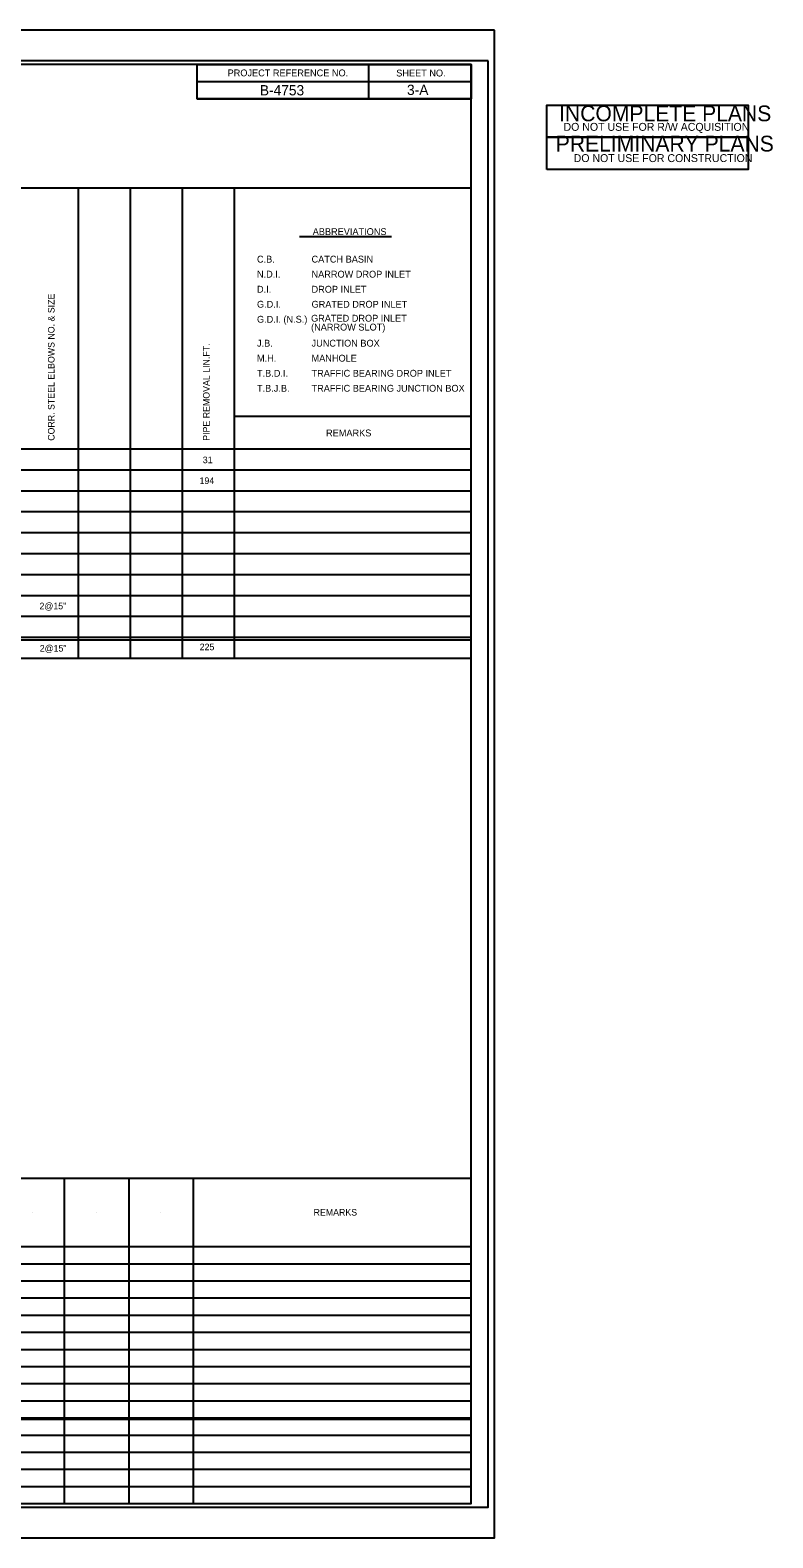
# Model space of a CAD drawing. Extents: x 573867 to 573943.6, y -53322.8 to -53274.5.
# Drawn here: x 573893.88 to 573904.73, y -53322.27 to -53300.27 of the extents above; entities that cross this region are included whole.
import ezdxf

# ---------------------------------------------------------------- set-up
doc = ezdxf.new("R2010")
doc.units = 0
for name, color, linetype in [('Sheet Cutting Line CELL', 7, 'Continuous'), ('Sheet Data Field CELL', 7, 'Continuous'), ('Sheet Pipe Summary CELL', 7, 'Continuous'), ('Sheet Pipe Summary Grid CELL', 7, 'Continuous'), ('Sheet Plot Border Inside CELL', 7, 'Continuous'), ('Sheet Plot Border Outside CELL', 7, 'Continuous'), ('Sheet Sticker Incomplete CELL', 7, 'Continuous'), ('Sheet Sticker Preliminary CELL', 7, 'Continuous'), ('Sheet Summary Combination CELL', 7, 'Continuous'), ('Sheet Summary Combination Grid CELL', 7, 'Continuous'), ('Sheet Summary Guardrail CELL', 7, 'Continuous')]:
    doc.layers.add(name, color=color, linetype=linetype)

msp = doc.modelspace()

# ---------------------------------------------------------------- linework, layer by layer
at = {"layer": 'Sheet Cutting Line CELL'}
for p, q in [((573900.663, -53300.271), (573866.983, -53300.271)), ((573866.983, -53322.271), (573900.663, -53322.271))]:
    msp.add_line(p, q, dxfattribs=at)
at = {"layer": 'Sheet Pipe Summary CELL'}
msp.add_line((573899.158, -53303.289), (573897.818, -53303.289), dxfattribs=at)
at = {"layer": 'Sheet Pipe Summary Grid CELL'}
for p, q in [((573900.323, -53302.578), (573870.323, -53302.58)), ((573894.588, -53309.44), (573894.587, -53302.579)), ((573894.588, -53309.44), (573894.587, -53302.579)), ((573895.348, -53309.44), (573895.347, -53302.579)), ((573895.348, -53309.44), (573895.347, -53302.579)), ((573896.108, -53309.44), (573896.107, -53302.579)), ((573896.108, -53309.44), (573896.107, -53302.579)), ((573896.868, -53309.44), (573896.867, -53302.579)), ((573896.868, -53309.44), (573896.867, -53302.579)), ((573900.323, -53305.91), (573896.868, -53305.91)), ((573900.323, -53306.386), (573870.323, -53306.386)), ((573900.323, -53306.692), (573870.323, -53306.692)), ((573900.323, -53306.997), (573870.323, -53306.997)), ((573900.323, -53307.302), (573870.323, -53307.302)), ((573900.323, -53307.608), (573870.323, -53307.608)), ((573900.323, -53307.913), (573870.323, -53307.913)), ((573900.323, -53308.219), (573870.323, -53308.219)), ((573900.323, -53308.524), (573870.323, -53308.524)), ((573900.323, -53308.829), (573870.323, -53308.829)), ((573900.323, -53309.135), (573870.323, -53309.135)), ((573900.323, -53309.44), (573870.323, -53309.44))]:
    msp.add_line(p, q, dxfattribs=at)
at = {"layer": 'Sheet Plot Border Inside CELL'}
msp.add_lwpolyline([(573900.573, -53300.72), (573867.243, -53300.72), (573867.243, -53321.822), (573900.573, -53321.822)], close=True, dxfattribs=at)
at = {"layer": 'Sheet Plot Border Outside CELL'}
msp.add_lwpolyline([(573900.663, -53300.271), (573866.983, -53300.271), (573866.983, -53322.271), (573900.663, -53322.271)], close=True, dxfattribs=at)
at = {"layer": 'Sheet Sticker Incomplete CELL'}
msp.add_lwpolyline([(573901.428, -53301.835), (573901.428, -53301.365), (573904.368, -53301.365), (573904.368, -53301.835)], close=True, dxfattribs=at)
at = {"layer": 'Sheet Sticker Preliminary CELL'}
msp.add_lwpolyline([(573901.428, -53302.305), (573901.428, -53301.835), (573904.368, -53301.835), (573904.368, -53302.305)], close=True, dxfattribs=at)
at = {"layer": 'Sheet Summary Combination CELL'}
for p, q in [((573898.823, -53300.772), (573898.823, -53301.272)), ((573896.322, -53301.022), (573900.323, -53301.022)), ((573896.322, -53301.272), (573900.323, -53301.272))]:
    msp.add_line(p, q, dxfattribs=at)
for points in [[(573900.323, -53300.771), (573870.323, -53300.771), (573870.323, -53321.771), (573900.323, -53321.771)], [(573896.322, -53300.771), (573900.323, -53300.771), (573900.323, -53301.272), (573896.322, -53301.272)]]:
    msp.add_lwpolyline(points, close=True, dxfattribs=at)
at = {"layer": 'Sheet Summary Combination Grid CELL'}
msp.add_line((573900.323, -53309.171), (573870.323, -53309.171), dxfattribs=at)
at = {"layer": 'Sheet Summary Guardrail CELL'}
for p, q in [((573870.323, -53317.021), (573900.323, -53317.021)), ((573894.381, -53317.021), (573894.381, -53321.771)), ((573895.321, -53317.021), (573895.321, -53321.771)), ((573896.261, -53317.021), (573896.261, -53321.771)), ((573893.911, -53317.521), (573893.911, -53317.521)), ((573894.851, -53317.521), (573894.851, -53317.521)), ((573895.791, -53317.521), (573895.791, -53317.521)), ((573870.323, -53318.021), (573900.323, -53318.021)), ((573870.323, -53318.271), (573900.323, -53318.271)), ((573870.323, -53318.521), (573900.323, -53318.521)), ((573870.323, -53318.771), (573900.323, -53318.771)), ((573870.323, -53319.021), (573900.323, -53319.021)), ((573870.323, -53319.271), (573900.323, -53319.271)), ((573870.323, -53319.521), (573900.323, -53319.521)), ((573876.353, -53319.771), (573900.323, -53319.771)), ((573870.323, -53320.021), (573900.323, -53320.021)), ((573870.323, -53320.271), (573900.323, -53320.271)), ((573870.323, -53320.521), (573900.323, -53320.521)), ((573870.323, -53320.539), (573900.323, -53320.539)), ((573876.353, -53320.771), (573900.323, -53320.771)), ((573870.323, -53321.021), (573900.323, -53321.021)), ((573870.323, -53321.271), (573900.323, -53321.271)), ((573870.323, -53321.521), (573900.323, -53321.521)), ((573870.323, -53321.771), (573900.323, -53321.771))]:
    msp.add_line(p, q, dxfattribs=at)

# ---------------------------------------------------------------- texts
at = {"layer": 'Sheet Data Field CELL'}
for s, p in [('B-4753', (573897.237, -53301.223)), ('3-A', (573899.386, -53301.217))]:
    msp.add_text(s, height=0.15, dxfattribs=at).set_placement(p)
at = {"layer": 'Sheet Pipe Summary CELL'}
for s, p in [('ABBREVIATIONS', (573898.009, -53303.261)), ('C.B.', (573897.195, -53303.663)), ('CATCH BASIN', (573897.992, -53303.663)), ('N.D.I.', (573897.195, -53303.882)), ('NARROW DROP INLET', (573897.992, -53303.882)), ('D.I.', (573897.195, -53304.102)), ('DROP INLET', (573897.992, -53304.102)), ('G.D.I.', (573897.195, -53304.321)), ('GRATED DROP INLET', (573897.992, -53304.321)), ('G.D.I. (N.S.)', (573897.195, -53304.54)), ('J.B.', (573897.195, -53304.889)), ('JUNCTION BOX', (573897.992, -53304.889)), ('M.H.', (573897.195, -53305.108)), ('MANHOLE', (573897.992, -53305.108)), ('T.B.D.I.', (573897.195, -53305.328)), ('TRAFFIC BEARING DROP INLET', (573897.992, -53305.328)), ('T.B.J.B.', (573897.195, -53305.547)), ('TRAFFIC BEARING JUNCTION BOX', (573897.992, -53305.547)), ('REMARKS', (573898.204, -53306.199))]:
    msp.add_text(s, height=0.1, dxfattribs=at).set_placement(p)
for s, height, rotation, p in [('CORR. STEEL ELBOWS NO. & SIZE', 0.096, 90, (573894.238, -53306.263)), ('GRATED DROP INLET', 0.1, 0.0274, (573897.985, -53304.525)), ('(NARROW SLOT)', 0.1, 0.0274, (573897.985, -53304.655)), ('PIPE REMOVAL LIN.FT.', 0.096, 90, (573896.503, -53306.263))]:
    msp.add_text(s, height=height, rotation=rotation, dxfattribs=at).set_placement(p)
at = {"layer": 'Sheet Sticker Incomplete CELL'}
for s, height, p in [('INCOMPLETE PLANS', 0.2304, (573901.607, -53301.601)), ('DO NOT USE FOR R/W ACQUISITION', 0.1152, (573901.672, -53301.74))]:
    msp.add_text(s, height=height, dxfattribs=at).set_placement(p)
at = {"layer": 'Sheet Sticker Preliminary CELL'}
for s, height, p in [('PRELIMINARY PLANS', 0.2304, (573901.558, -53302.042)), ('DO NOT USE FOR CONSTRUCTION', 0.1152, (573901.82, -53302.196))]:
    msp.add_text(s, height=height, dxfattribs=at).set_placement(p)
at = {"layer": 'Sheet Summary Combination CELL'}
for s, height, p in [('PROJECT REFERENCE NO.', 0.1, (573896.766, -53300.945)), ('SHEET NO.', 0.1, (573899.229, -53300.947)), ('31', 0.096, (573896.404, -53306.59)), ('194', 0.096, (573896.356, -53306.893)), ('2@15"', 0.096, (573894.019, -53308.722)), ('2@15"', 0.096, (573894.023, -53309.339)), ('225', 0.096, (573896.358, -53309.319))]:
    msp.add_text(s, height=height, dxfattribs=at).set_placement(p)
at = {"layer": 'Sheet Summary Guardrail CELL'}
msp.add_text('REMARKS', height=0.096, dxfattribs=at).set_placement((573898.022, -53317.569))

doc.saveas('drawing.dxf')
